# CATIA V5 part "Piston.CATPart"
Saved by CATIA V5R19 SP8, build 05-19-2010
Part number: Piston
Publications: "Longueur_tige"
Bounding box of the stored display mesh (mm): x -22 to 22, y -90 to 11.864, z -14.381 to 14.381
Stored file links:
  E:\IAO_2010\iao\IAO_MMS_Groupe2\IAO_MMS_Groupe2\OK\nmoissenet\nmoissenet\nmoissenet\Piston.CATPart
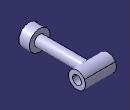
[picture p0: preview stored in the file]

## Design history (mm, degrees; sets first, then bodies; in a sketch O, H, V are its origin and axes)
Parameters
  Longueur_tige = 90 mm
Body1 (main body)
  Sketch1 on yz-plane, origin (0, 0, 0), H (0, 1, 0), V (0, 0, 1)
    point P1 (0, 0)
    line L1 (-90, -14.5) -> (-75, -14.5)
    line L2 (-75, -14.5) -> (-75, -7.5)
    line L3 (-75, -7.5) -> (0, -7.5)
    line L4 (0, -7.5) -> (0, 0)
    line L5 (-90, 0) -> (0, 0)
    line L6 (-90, 0) -> (-90, -14.5)
    length L6 = 14.5
    length L4 = 7.5
    length L1 = 15
    length L5 = 90 {= Longueur_tige}
    coincidence: P1 H, L4 V
    horizontal: L1 H, L3 H, L5 H
    vertical: L2 V, L4 V, L6 V
  Shaft1: profile Sketch1, axis Sketch1.L5, angle 360
  Sketch2 on xy-plane, origin (0, 0, 0), H (1, 0, 0), V (0, 1, 0)
    point P1 (-12, 24)
    point P2 (-12, -12)
    line L1 (22, 0) -> (22, 12)
    line L2 (22, 12) -> (-22, 12)
    line L3 (-22, 12) -> (-22, 0)
    point P3 (12, -12)
    line L4 (-22, 0) -> (22, 0)
    distance V L3 = 22
    distance L1 L3 = 44
    length L1 = 12
    horizontal: L2 H, L4 H
    vertical: L1 V, L3 V
  Shaft2: profile Sketch2, axis Sketch2.L4, angle 360
  Sketch3 on face of Shaft2 from Sketch2.L3, origin (-22, 0, 0), H (0, -1, 0), V (0, 0, 1)
    circle A1 centre (0, 0) radius 6.5
    radius A1 = 6.5
  Pocket1: profile Sketch3, direction (1, 0, 0), through (limit type 6)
